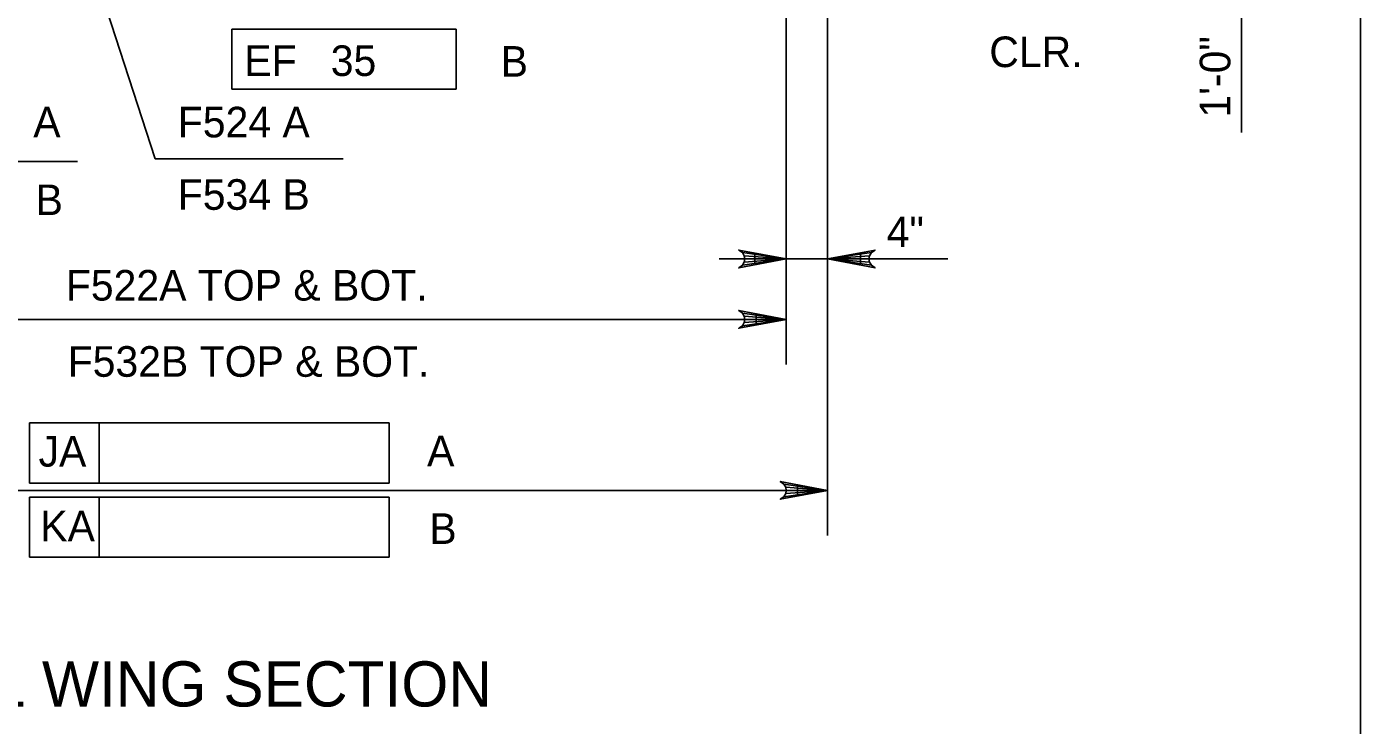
# Model space of a CAD drawing. Extents: x 638340 to 640242, y 295465 to 298435.
# Drawn here: x 639971.8 to 640102.5, y 298140 to 298208.5 of the extents above; entities that cross this region are included whole.
import ezdxf

# ---------------------------------------------------------------- set-up
doc = ezdxf.new("R2010")
doc.units = 0
for name, color, linetype in [('2', 7, 'Continuous'), ('4', 7, 'Continuous'), ('Level 3', 7, 'Continuous'), ('Level 4', 7, 'Continuous')]:
    doc.layers.add(name, color=color, linetype=linetype)

msp = doc.modelspace()

# ---------------------------------------------------------------- linework, layer by layer
at = {"layer": '2'}
msp.add_line((640102.46, 298420.46), (640102.46, 297856.46), dxfattribs=at)
at = {"layer": 'Level 3'}
msp.add_line((640090.81, 298215.06), (640090.81, 298198.16), dxfattribs=at)
at = {"layer": 'Level 4'}
for p, q in [((639969.96, 298239.78), (639984.38, 298195.59)), ((640046.2, 298221.1), (640046.2, 298175.43)), ((640050.26, 298216.56), (640050.26, 298158.66)), ((639991.88, 298208.31), (640013.87, 298208.31)), ((639991.88, 298202.42), (639991.88, 298208.31)), ((640013.87, 298208.31), (640013.87, 298202.42)), ((640013.87, 298202.42), (639991.88, 298202.42)), ((639947.13, 298195.32), (639976.74, 298195.32)), ((639984.38, 298195.59), (640002.77, 298195.59)), ((640050.26, 298196.29), (640050.26, 298184.82)), ((640046.2, 298185.77), (640039.62, 298185.77)), ((640046.2, 298185.77), (640062.05, 298185.77)), ((639940.26, 298179.85), (640046.2, 298179.85)), ((639972.05, 298169.69), (640007.28, 298169.69)), ((639972.05, 298163.8), (639972.05, 298169.69)), ((639978.88, 298163.8), (639978.88, 298169.69)), ((640007.28, 298169.69), (640007.28, 298163.8)), ((639936.2, 298163.08), (640050.26, 298163.08)), ((640007.28, 298163.8), (639972.05, 298163.8)), ((639972.05, 298162.42), (640007.28, 298162.42)), ((639972.05, 298156.53), (639972.05, 298162.42)), ((639978.88, 298156.53), (639978.88, 298162.42)), ((640007.28, 298162.42), (640007.28, 298156.53)), ((640007.28, 298156.53), (639972.05, 298156.53))]:
    msp.add_line(p, q, dxfattribs=at)
for points in [[(640046.2, 298185.77), (640041.55, 298184.9), (640041.91, 298185.15), (640042.09, 298185.46), (640042.15, 298185.77), (640042.09, 298186.08), (640041.91, 298186.39), (640041.55, 298186.64), (640046.2, 298185.77), (640041.91, 298186.39), (640042.09, 298186.08), (640046.2, 298185.77), (640042.15, 298185.77), (640042.09, 298185.46), (640046.2, 298185.77), (640041.91, 298185.15)], [(640050.26, 298185.77), (640054.91, 298186.64), (640054.55, 298186.39), (640054.37, 298186.08), (640054.31, 298185.77), (640054.37, 298185.46), (640054.55, 298185.15), (640054.91, 298184.9), (640050.26, 298185.77), (640054.55, 298185.15), (640054.37, 298185.46), (640050.26, 298185.77), (640054.31, 298185.77), (640054.37, 298186.08), (640050.26, 298185.77), (640054.55, 298186.39)], [(640046.2, 298179.85), (640041.55, 298178.98), (640041.91, 298179.22), (640042.09, 298179.54), (640042.15, 298179.85), (640042.09, 298180.16), (640041.91, 298180.47), (640041.55, 298180.72), (640046.2, 298179.85), (640041.91, 298180.47), (640042.09, 298180.16), (640046.2, 298179.85), (640042.15, 298179.85), (640042.09, 298179.54), (640046.2, 298179.85), (640041.91, 298179.22)], [(640050.26, 298163.08), (640045.61, 298162.21), (640045.96, 298162.45), (640046.15, 298162.77), (640046.2, 298163.08), (640046.15, 298163.39), (640045.96, 298163.7), (640045.61, 298163.95), (640050.26, 298163.08), (640045.96, 298163.7), (640046.15, 298163.39), (640050.26, 298163.08), (640046.2, 298163.08), (640046.15, 298162.77), (640050.26, 298163.08), (640045.96, 298162.45)]]:
    msp.add_lwpolyline(points, dxfattribs=at)
for points in [[(640043.12, 298185.28), (640043.12, 298186.26), (640046.07, 298185.77)], [(640053.48, 298186.26), (640053.48, 298185.28), (640050.53, 298185.77)], [(640043.25, 298180.34), (640043.25, 298179.36), (640046.2, 298179.85)], [(640047.31, 298163.57), (640047.31, 298162.59), (640050.26, 298163.08)]]:
    msp.add_lwpolyline(points, close=True, dxfattribs=at)

# ---------------------------------------------------------------- texts
at = {"layer": '4'}
msp.add_text('TYPICAL WING SECTION', height=4.4294, dxfattribs=at).set_placement((639946.94, 298141.89))
at = {"layer": 'Level 3'}
for s, p in [('CLR.', (640066.1, 298204.58)), ('4"', (640056.04, 298186.93))]:
    msp.add_text(s, height=3, dxfattribs=at).set_placement(p)
msp.add_text('1\'-0"', height=3, rotation=90, dxfattribs=at).set_placement((640089.72, 298199.63))
at = {"layer": 'Level 4'}
for s, height, p in [('EF   35', 3, (639993.1, 298203.71)), ('B', 3, (640018.22, 298203.64)), ('A', 3, (639972.42, 298197.7)), ('F524 A', 3, (639986.58, 298197.69)), ('B', 3, (639972.65, 298190.07)), ('F534 B', 3, (639986.58, 298190.59)), ('F522A TOP & BOT.', 3.0001, (639975.61, 298181.69)), ('F532B TOP & BOT.', 3.0001, (639975.79, 298174.22)), ('JA', 3, (639972.94, 298165.41)), ('A', 3, (640011.01, 298165.45)), ('KA', 3, (639973.11, 298158.08)), ('B', 3, (640011.23, 298157.83))]:
    msp.add_text(s, height=height, dxfattribs=at).set_placement(p)

doc.saveas('drawing.dxf')
